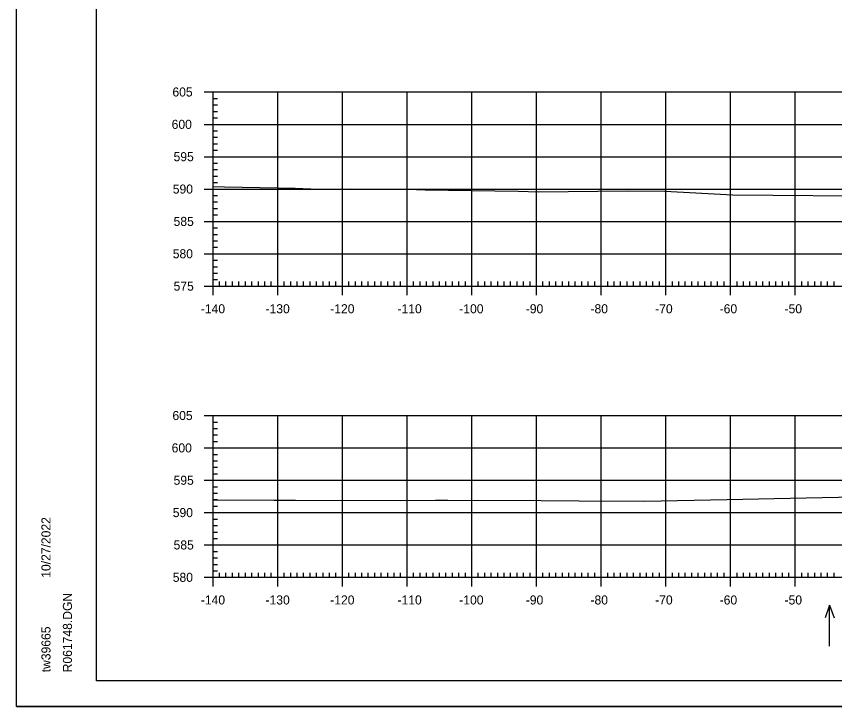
# Model space of a CAD drawing. Extents: x 961436 to 1372525, y 380079 to 2027791.
# Drawn here: x 1370463.4 to 1370589.9, y 380109.1 to 380215.7 of the extents above; entities that cross this region are included whole.
import ezdxf

# ---------------------------------------------------------------- set-up
doc = ezdxf.new("R2010")
doc.units = 0
for name, color, linetype in [('R_Axis', 7, 'Continuous'), ('R_Axis Annot', 7, 'Continuous'), ('R_Exist Surface', 7, 'Continuous'), ('R_Grid', 7, 'Continuous'), ('R_No Plot', 7, 'Continuous'), ('R_Water Annot', 7, 'Continuous')]:
    doc.layers.add(name, color=color, linetype=linetype)

msp = doc.modelspace()

# ---------------------------------------------------------------- linework, layer by layer
at = {"layer": 'R_Axis'}
for p, q in [((1370492.41, 380204.06), (1370495.21, 380204.06)), ((1370493.81, 380174.06), (1370493.81, 380204.06)), ((1370493.81, 380203.06), (1370494.51, 380203.06)), ((1370493.81, 380202.06), (1370494.51, 380202.06)), ((1370493.81, 380201.06), (1370494.51, 380201.06)), ((1370493.81, 380200.06), (1370494.51, 380200.06)), ((1370492.41, 380199.06), (1370495.21, 380199.06)), ((1370493.81, 380198.06), (1370494.51, 380198.06)), ((1370493.81, 380197.06), (1370494.51, 380197.06)), ((1370493.81, 380196.06), (1370494.51, 380196.06)), ((1370493.81, 380195.06), (1370494.51, 380195.06)), ((1370492.41, 380194.06), (1370495.21, 380194.06)), ((1370493.81, 380193.06), (1370494.51, 380193.06)), ((1370493.81, 380192.06), (1370494.51, 380192.06)), ((1370493.81, 380191.06), (1370494.51, 380191.06)), ((1370493.81, 380190.06), (1370494.51, 380190.06)), ((1370492.41, 380189.06), (1370495.21, 380189.06)), ((1370493.81, 380188.06), (1370494.51, 380188.06)), ((1370493.81, 380187.06), (1370494.51, 380187.06)), ((1370493.81, 380186.06), (1370494.51, 380186.06)), ((1370493.81, 380185.06), (1370494.51, 380185.06)), ((1370492.41, 380184.06), (1370495.21, 380184.06)), ((1370493.81, 380183.06), (1370494.51, 380183.06)), ((1370493.81, 380182.06), (1370494.51, 380182.06)), ((1370493.81, 380181.06), (1370494.51, 380181.06)), ((1370493.81, 380180.06), (1370494.51, 380180.06)), ((1370492.41, 380179.06), (1370495.21, 380179.06)), ((1370493.81, 380178.06), (1370494.51, 380178.06)), ((1370493.81, 380177.06), (1370494.51, 380177.06)), ((1370493.81, 380176.06), (1370494.51, 380176.06)), ((1370493.81, 380172.66), (1370493.81, 380175.46)), ((1370493.81, 380175.06), (1370494.51, 380175.06)), ((1370494.81, 380174.06), (1370494.81, 380174.76)), ((1370495.81, 380174.06), (1370495.81, 380174.76)), ((1370496.81, 380174.06), (1370496.81, 380174.76)), ((1370497.81, 380174.06), (1370497.81, 380174.76)), ((1370498.81, 380174.06), (1370498.81, 380174.76)), ((1370499.81, 380174.06), (1370499.81, 380174.76)), ((1370500.81, 380174.06), (1370500.81, 380174.76)), ((1370501.81, 380174.06), (1370501.81, 380174.76)), ((1370502.81, 380174.06), (1370502.81, 380174.76)), ((1370503.81, 380172.66), (1370503.81, 380175.46)), ((1370504.81, 380174.06), (1370504.81, 380174.76)), ((1370505.81, 380174.06), (1370505.81, 380174.76)), ((1370506.81, 380174.06), (1370506.81, 380174.76)), ((1370507.81, 380174.06), (1370507.81, 380174.76)), ((1370508.81, 380174.06), (1370508.81, 380174.76)), ((1370509.81, 380174.06), (1370509.81, 380174.76)), ((1370510.81, 380174.06), (1370510.81, 380174.76)), ((1370511.81, 380174.06), (1370511.81, 380174.76)), ((1370512.81, 380174.06), (1370512.81, 380174.76)), ((1370513.81, 380172.66), (1370513.81, 380175.46)), ((1370514.81, 380174.06), (1370514.81, 380174.76)), ((1370515.81, 380174.06), (1370515.81, 380174.76)), ((1370516.81, 380174.06), (1370516.81, 380174.76)), ((1370517.81, 380174.06), (1370517.81, 380174.76)), ((1370518.81, 380174.06), (1370518.81, 380174.76)), ((1370519.81, 380174.06), (1370519.81, 380174.76)), ((1370520.81, 380174.06), (1370520.81, 380174.76)), ((1370521.81, 380174.06), (1370521.81, 380174.76)), ((1370522.81, 380174.06), (1370522.81, 380174.76)), ((1370523.81, 380172.66), (1370523.81, 380175.46)), ((1370524.81, 380174.06), (1370524.81, 380174.76)), ((1370525.81, 380174.06), (1370525.81, 380174.76)), ((1370526.81, 380174.06), (1370526.81, 380174.76)), ((1370527.81, 380174.06), (1370527.81, 380174.76)), ((1370528.81, 380174.06), (1370528.81, 380174.76)), ((1370529.81, 380174.06), (1370529.81, 380174.76)), ((1370530.81, 380174.06), (1370530.81, 380174.76)), ((1370531.81, 380174.06), (1370531.81, 380174.76)), ((1370532.81, 380174.06), (1370532.81, 380174.76)), ((1370533.81, 380172.66), (1370533.81, 380175.46)), ((1370534.81, 380174.06), (1370534.81, 380174.76)), ((1370535.81, 380174.06), (1370535.81, 380174.76)), ((1370536.81, 380174.06), (1370536.81, 380174.76)), ((1370537.81, 380174.06), (1370537.81, 380174.76)), ((1370538.81, 380174.06), (1370538.81, 380174.76)), ((1370539.81, 380174.06), (1370539.81, 380174.76)), ((1370540.81, 380174.06), (1370540.81, 380174.76)), ((1370541.81, 380174.06), (1370541.81, 380174.76)), ((1370542.81, 380174.06), (1370542.81, 380174.76)), ((1370543.81, 380172.66), (1370543.81, 380175.46)), ((1370544.81, 380174.06), (1370544.81, 380174.76)), ((1370545.81, 380174.06), (1370545.81, 380174.76)), ((1370546.81, 380174.06), (1370546.81, 380174.76)), ((1370547.81, 380174.06), (1370547.81, 380174.76)), ((1370548.81, 380174.06), (1370548.81, 380174.76)), ((1370549.81, 380174.06), (1370549.81, 380174.76)), ((1370550.81, 380174.06), (1370550.81, 380174.76)), ((1370551.81, 380174.06), (1370551.81, 380174.76)), ((1370552.81, 380174.06), (1370552.81, 380174.76)), ((1370553.81, 380172.66), (1370553.81, 380175.46)), ((1370554.81, 380174.06), (1370554.81, 380174.76)), ((1370555.81, 380174.06), (1370555.81, 380174.76)), ((1370556.81, 380174.06), (1370556.81, 380174.76)), ((1370557.81, 380174.06), (1370557.81, 380174.76)), ((1370558.81, 380174.06), (1370558.81, 380174.76)), ((1370559.81, 380174.06), (1370559.81, 380174.76)), ((1370560.81, 380174.06), (1370560.81, 380174.76)), ((1370561.81, 380174.06), (1370561.81, 380174.76)), ((1370562.81, 380174.06), (1370562.81, 380174.76)), ((1370563.81, 380172.66), (1370563.81, 380175.46)), ((1370564.81, 380174.06), (1370564.81, 380174.76)), ((1370565.81, 380174.06), (1370565.81, 380174.76)), ((1370566.81, 380174.06), (1370566.81, 380174.76)), ((1370567.81, 380174.06), (1370567.81, 380174.76)), ((1370568.81, 380174.06), (1370568.81, 380174.76)), ((1370569.81, 380174.06), (1370569.81, 380174.76)), ((1370570.81, 380174.06), (1370570.81, 380174.76)), ((1370571.81, 380174.06), (1370571.81, 380174.76)), ((1370572.81, 380174.06), (1370572.81, 380174.76)), ((1370573.81, 380172.66), (1370573.81, 380175.46)), ((1370574.81, 380174.06), (1370574.81, 380174.76)), ((1370575.81, 380174.06), (1370575.81, 380174.76)), ((1370576.81, 380174.06), (1370576.81, 380174.76)), ((1370577.81, 380174.06), (1370577.81, 380174.76)), ((1370578.81, 380174.06), (1370578.81, 380174.76)), ((1370579.81, 380174.06), (1370579.81, 380174.76)), ((1370580.81, 380174.06), (1370580.81, 380174.76)), ((1370581.81, 380174.06), (1370581.81, 380174.76)), ((1370582.81, 380174.06), (1370582.81, 380174.76)), ((1370583.81, 380172.66), (1370583.81, 380175.46)), ((1370584.81, 380174.06), (1370584.81, 380174.76)), ((1370585.81, 380174.06), (1370585.81, 380174.76)), ((1370586.81, 380174.06), (1370586.81, 380174.76)), ((1370587.81, 380174.06), (1370587.81, 380174.76)), ((1370588.81, 380174.06), (1370588.81, 380174.76)), ((1370589.81, 380174.06), (1370589.81, 380174.76)), ((1370492.41, 380174.06), (1370495.21, 380174.06)), ((1370493.81, 380174.06), (1370773.81, 380174.06)), ((1370492.41, 380154.06), (1370495.21, 380154.06)), ((1370493.81, 380129.06), (1370493.81, 380154.06)), ((1370493.81, 380153.06), (1370494.51, 380153.06)), ((1370493.81, 380152.06), (1370494.51, 380152.06)), ((1370493.81, 380151.06), (1370494.51, 380151.06)), ((1370492.41, 380149.06), (1370495.21, 380149.06)), ((1370493.81, 380150.06), (1370494.51, 380150.06)), ((1370493.81, 380148.06), (1370494.51, 380148.06)), ((1370493.81, 380147.06), (1370494.51, 380147.06)), ((1370493.81, 380146.06), (1370494.51, 380146.06)), ((1370492.41, 380144.06), (1370495.21, 380144.06)), ((1370493.81, 380145.06), (1370494.51, 380145.06)), ((1370493.81, 380143.06), (1370494.51, 380143.06)), ((1370493.81, 380142.06), (1370494.51, 380142.06)), ((1370493.81, 380141.06), (1370494.51, 380141.06)), ((1370492.41, 380139.06), (1370495.21, 380139.06)), ((1370493.81, 380140.06), (1370494.51, 380140.06)), ((1370493.81, 380138.06), (1370494.51, 380138.06)), ((1370493.81, 380137.06), (1370494.51, 380137.06)), ((1370493.81, 380136.06), (1370494.51, 380136.06)), ((1370493.81, 380135.06), (1370494.51, 380135.06)), ((1370492.41, 380134.06), (1370495.21, 380134.06)), ((1370493.81, 380133.06), (1370494.51, 380133.06)), ((1370493.81, 380132.06), (1370494.51, 380132.06)), ((1370493.81, 380131.06), (1370494.51, 380131.06)), ((1370493.81, 380127.66), (1370493.81, 380130.46)), ((1370493.81, 380130.06), (1370494.51, 380130.06)), ((1370503.81, 380127.66), (1370503.81, 380130.46)), ((1370513.81, 380127.66), (1370513.81, 380130.46)), ((1370523.81, 380127.66), (1370523.81, 380130.46)), ((1370533.81, 380127.66), (1370533.81, 380130.46)), ((1370543.81, 380127.66), (1370543.81, 380130.46)), ((1370553.81, 380127.66), (1370553.81, 380130.46)), ((1370563.81, 380127.66), (1370563.81, 380130.46)), ((1370573.81, 380127.66), (1370573.81, 380130.46)), ((1370583.81, 380127.66), (1370583.81, 380130.46)), ((1370492.41, 380129.06), (1370495.21, 380129.06)), ((1370493.81, 380129.06), (1370773.81, 380129.06)), ((1370494.81, 380129.06), (1370494.81, 380129.76)), ((1370495.81, 380129.06), (1370495.81, 380129.76)), ((1370496.81, 380129.06), (1370496.81, 380129.76)), ((1370497.81, 380129.06), (1370497.81, 380129.76)), ((1370498.81, 380129.06), (1370498.81, 380129.76)), ((1370499.81, 380129.06), (1370499.81, 380129.76)), ((1370500.81, 380129.06), (1370500.81, 380129.76)), ((1370501.81, 380129.06), (1370501.81, 380129.76)), ((1370502.81, 380129.06), (1370502.81, 380129.76)), ((1370504.81, 380129.06), (1370504.81, 380129.76)), ((1370505.81, 380129.06), (1370505.81, 380129.76)), ((1370506.81, 380129.06), (1370506.81, 380129.76)), ((1370507.81, 380129.06), (1370507.81, 380129.76)), ((1370508.81, 380129.06), (1370508.81, 380129.76)), ((1370509.81, 380129.06), (1370509.81, 380129.76)), ((1370510.81, 380129.06), (1370510.81, 380129.76)), ((1370511.81, 380129.06), (1370511.81, 380129.76)), ((1370512.81, 380129.06), (1370512.81, 380129.76)), ((1370514.81, 380129.06), (1370514.81, 380129.76)), ((1370515.81, 380129.06), (1370515.81, 380129.76)), ((1370516.81, 380129.06), (1370516.81, 380129.76)), ((1370517.81, 380129.06), (1370517.81, 380129.76)), ((1370518.81, 380129.06), (1370518.81, 380129.76)), ((1370519.81, 380129.06), (1370519.81, 380129.76)), ((1370520.81, 380129.06), (1370520.81, 380129.76)), ((1370521.81, 380129.06), (1370521.81, 380129.76)), ((1370522.81, 380129.06), (1370522.81, 380129.76)), ((1370524.81, 380129.06), (1370524.81, 380129.76)), ((1370525.81, 380129.06), (1370525.81, 380129.76)), ((1370526.81, 380129.06), (1370526.81, 380129.76)), ((1370527.81, 380129.06), (1370527.81, 380129.76)), ((1370528.81, 380129.06), (1370528.81, 380129.76)), ((1370529.81, 380129.06), (1370529.81, 380129.76)), ((1370530.81, 380129.06), (1370530.81, 380129.76)), ((1370531.81, 380129.06), (1370531.81, 380129.76)), ((1370532.81, 380129.06), (1370532.81, 380129.76)), ((1370534.81, 380129.06), (1370534.81, 380129.76)), ((1370535.81, 380129.06), (1370535.81, 380129.76)), ((1370536.81, 380129.06), (1370536.81, 380129.76)), ((1370537.81, 380129.06), (1370537.81, 380129.76)), ((1370538.81, 380129.06), (1370538.81, 380129.76)), ((1370539.81, 380129.06), (1370539.81, 380129.76)), ((1370540.81, 380129.06), (1370540.81, 380129.76)), ((1370541.81, 380129.06), (1370541.81, 380129.76)), ((1370542.81, 380129.06), (1370542.81, 380129.76)), ((1370544.81, 380129.06), (1370544.81, 380129.76)), ((1370545.81, 380129.06), (1370545.81, 380129.76)), ((1370546.81, 380129.06), (1370546.81, 380129.76)), ((1370547.81, 380129.06), (1370547.81, 380129.76)), ((1370548.81, 380129.06), (1370548.81, 380129.76)), ((1370549.81, 380129.06), (1370549.81, 380129.76)), ((1370550.81, 380129.06), (1370550.81, 380129.76)), ((1370551.81, 380129.06), (1370551.81, 380129.76)), ((1370552.81, 380129.06), (1370552.81, 380129.76)), ((1370554.81, 380129.06), (1370554.81, 380129.76)), ((1370555.81, 380129.06), (1370555.81, 380129.76)), ((1370556.81, 380129.06), (1370556.81, 380129.76)), ((1370557.81, 380129.06), (1370557.81, 380129.76)), ((1370558.81, 380129.06), (1370558.81, 380129.76)), ((1370559.81, 380129.06), (1370559.81, 380129.76)), ((1370560.81, 380129.06), (1370560.81, 380129.76)), ((1370561.81, 380129.06), (1370561.81, 380129.76)), ((1370562.81, 380129.06), (1370562.81, 380129.76)), ((1370564.81, 380129.06), (1370564.81, 380129.76)), ((1370565.81, 380129.06), (1370565.81, 380129.76)), ((1370566.81, 380129.06), (1370566.81, 380129.76)), ((1370567.81, 380129.06), (1370567.81, 380129.76)), ((1370568.81, 380129.06), (1370568.81, 380129.76)), ((1370569.81, 380129.06), (1370569.81, 380129.76)), ((1370570.81, 380129.06), (1370570.81, 380129.76)), ((1370571.81, 380129.06), (1370571.81, 380129.76)), ((1370572.81, 380129.06), (1370572.81, 380129.76)), ((1370574.81, 380129.06), (1370574.81, 380129.76)), ((1370575.81, 380129.06), (1370575.81, 380129.76)), ((1370576.81, 380129.06), (1370576.81, 380129.76)), ((1370577.81, 380129.06), (1370577.81, 380129.76)), ((1370578.81, 380129.06), (1370578.81, 380129.76)), ((1370579.81, 380129.06), (1370579.81, 380129.76)), ((1370580.81, 380129.06), (1370580.81, 380129.76)), ((1370581.81, 380129.06), (1370581.81, 380129.76)), ((1370582.81, 380129.06), (1370582.81, 380129.76)), ((1370584.81, 380129.06), (1370584.81, 380129.76)), ((1370585.81, 380129.06), (1370585.81, 380129.76)), ((1370586.81, 380129.06), (1370586.81, 380129.76)), ((1370587.81, 380129.06), (1370587.81, 380129.76)), ((1370588.81, 380129.06), (1370588.81, 380129.76)), ((1370589.81, 380129.06), (1370589.81, 380129.76))]:
    msp.add_line(p, q, dxfattribs=at)
at = {"layer": 'R_Exist Surface'}
for points in [[(1370493.81, 380189.46), (1370495.59, 380189.41), (1370506.51, 380189.22), (1370510.1, 380189.02), (1370515.03, 380189.1), (1370525.26, 380188.98), (1370526.62, 380188.94), (1370540.96, 380188.74), (1370544.1, 380188.65), (1370557.89, 380188.79), (1370563.64, 380188.72), (1370574.15, 380188.16), (1370598.96, 380187.95)], [(1370493.81, 380141.02), (1370503.23, 380140.98), (1370506.57, 380140.98), (1370522.84, 380140.92), (1370528.19, 380140.98), (1370530.1, 380140.96), (1370544.52, 380140.94), (1370550.42, 380140.86), (1370560.51, 380140.83), (1370573.26, 380141.09), (1370580.54, 380141.23), (1370597.9, 380141.59)]]:
    msp.add_lwpolyline(points, dxfattribs=at)
at = {"layer": 'R_Grid'}
for p, q in [((1370493.81, 380204.06), (1370773.81, 380204.06)), ((1370493.81, 380174.06), (1370493.81, 380204.06)), ((1370503.81, 380174.06), (1370503.81, 380204.06)), ((1370513.81, 380174.06), (1370513.81, 380204.06)), ((1370523.81, 380174.06), (1370523.81, 380204.06)), ((1370533.81, 380174.06), (1370533.81, 380204.06)), ((1370543.81, 380174.06), (1370543.81, 380204.06)), ((1370553.81, 380174.06), (1370553.81, 380204.06)), ((1370563.81, 380174.06), (1370563.81, 380204.06)), ((1370573.81, 380174.06), (1370573.81, 380204.06)), ((1370583.81, 380174.06), (1370583.81, 380204.06)), ((1370493.81, 380199.06), (1370773.81, 380199.06)), ((1370493.81, 380194.06), (1370773.81, 380194.06)), ((1370493.81, 380189.06), (1370773.81, 380189.06)), ((1370493.81, 380184.06), (1370773.81, 380184.06)), ((1370493.81, 380179.06), (1370773.81, 380179.06)), ((1370493.81, 380174.06), (1370773.81, 380174.06)), ((1370493.81, 380154.06), (1370773.81, 380154.06)), ((1370493.81, 380129.06), (1370493.81, 380154.06)), ((1370503.81, 380129.06), (1370503.81, 380154.06)), ((1370513.81, 380129.06), (1370513.81, 380154.06)), ((1370523.81, 380129.06), (1370523.81, 380154.06)), ((1370533.81, 380129.06), (1370533.81, 380154.06)), ((1370543.81, 380129.06), (1370543.81, 380154.06)), ((1370553.81, 380129.06), (1370553.81, 380154.06)), ((1370563.81, 380129.06), (1370563.81, 380154.06)), ((1370573.81, 380129.06), (1370573.81, 380154.06)), ((1370583.81, 380129.06), (1370583.81, 380154.06)), ((1370493.81, 380149.06), (1370773.81, 380149.06)), ((1370493.81, 380144.06), (1370773.81, 380144.06)), ((1370493.81, 380139.06), (1370773.81, 380139.06)), ((1370493.81, 380134.06), (1370773.81, 380134.06)), ((1370493.81, 380129.06), (1370773.81, 380129.06))]:
    msp.add_line(p, q, dxfattribs=at)
at = {"layer": 'R_No Plot'}
for p, q in [((1370475.81, 380113.06), (1370475.81, 380318.52)), ((1370475.81, 380113.06), (1370475.81, 380113.06)), ((1370791.99, 380113.06), (1370475.81, 380113.06)), ((1370463.41, 380109.08), (1370796.74, 380109.08))]:
    msp.add_line(p, q, dxfattribs=at)
for points in [[(1370463.4, 380322.41), (1370796.74, 380322.41), (1370796.74, 380109.08), (1370463.4, 380109.08)], [(1370709.73, 380318.52), (1370729.35, 380318.52), (1370729.35, 380308.64), (1370745.46, 380308.64), (1370768.66, 380308.64), (1370768.78, 380280.48), (1370791.99, 380280.48), (1370791.99, 380113.06), (1370475.81, 380113.06), (1370475.81, 380318.52)]]:
    msp.add_lwpolyline(points, close=True, dxfattribs=at)
at = {"layer": 'R_Water Annot'}
for p, q in [((1370589.12, 380124.73), (1370588.42, 380122.81)), ((1370589.12, 380118.44), (1370589.12, 380124.73)), ((1370589.12, 380124.73), (1370589.82, 380122.81))]:
    msp.add_line(p, q, dxfattribs=at)

# ---------------------------------------------------------------- texts
at = {"layer": 'R_Axis Annot'}
for s, p in [('605', (1370487.53, 380203.36)), ('600', (1370487.41, 380198.36)), ('595', (1370487.71, 380193.36)), ('590', (1370487.58, 380188.36)), ('585', (1370487.71, 380183.36)), ('580', (1370487.58, 380178.36)), ('575', (1370487.71, 380173.36)), ('-140', (1370491.92, 380169.86)), ('-130', (1370501.92, 380169.86)), ('-120', (1370511.92, 380169.86)), ('-110', (1370522.32, 380169.86)), ('-100', (1370531.87, 380169.86)), ('-90', (1370542.15, 380169.86)), ('-80', (1370552.15, 380169.86)), ('-70', (1370562.15, 380169.86)), ('-60', (1370572.12, 380169.86)), ('-50', (1370582.15, 380169.86)), ('605', (1370487.53, 380153.36)), ('600', (1370487.41, 380148.36)), ('595', (1370487.71, 380143.36)), ('590', (1370487.58, 380138.36)), ('585', (1370487.71, 380133.36)), ('580', (1370487.58, 380128.36)), ('-140', (1370491.92, 380124.86)), ('-130', (1370501.92, 380124.86)), ('-120', (1370511.92, 380124.86)), ('-110', (1370522.32, 380124.86)), ('-100', (1370531.87, 380124.86)), ('-90', (1370542.15, 380124.86)), ('-80', (1370552.15, 380124.86)), ('-70', (1370562.15, 380124.86)), ('-60', (1370572.12, 380124.86)), ('-50', (1370582.15, 380124.86))]:
    msp.add_text(s, height=1.4, dxfattribs=at).set_placement(p)
at = {"layer": 'R_No Plot'}
for s, p in [('10/27/2022', (1370468.68, 380128.99)), ('R061748.DGN', (1370472, 380114.38)), ('tw39665', (1370468.68, 380114.38))]:
    msp.add_text(s, height=1.4, rotation=90, dxfattribs=at).set_placement(p)

doc.saveas('drawing.dxf')
